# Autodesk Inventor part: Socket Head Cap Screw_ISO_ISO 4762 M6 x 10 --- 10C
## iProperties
Created: 2011-02
Part Number: Socket Head Cap Screw_ISO_ISO 4762 M6 x 10 --- 10C
Document SubType Name: Modeling
Designer: eric
Density: 1 g/cm^3
Author: eric
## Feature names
1. Base1
